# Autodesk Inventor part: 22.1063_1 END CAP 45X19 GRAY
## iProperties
Created: 2007-01
Part Number: 22.1063_1 END CAP 45X19 GRAY
Document SubType Name: Modeling
Designer: Andy Moles
Material: ABS Plastic
Mass: 2.6525 g
Surface Area: 20.0463 cm^2
Volume: 2.50236 cm^3
Density: 1.06 g/cm^3
Author: Andy Moles
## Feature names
1. Extrusion1
2. Fillet1
3. Fillet2
4. Extrusion2
5. Fillet3
6. Mirror1
